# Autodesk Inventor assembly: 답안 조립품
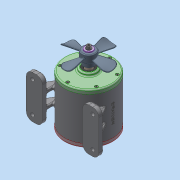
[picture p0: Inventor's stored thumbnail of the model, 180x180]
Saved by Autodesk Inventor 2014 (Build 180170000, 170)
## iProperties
Created: 2024-02
Part Number: 답안 조립품
Document SubType Name: Assembly
Designer: dg
Mass: 3108.48 g
Surface Area: 2333.46 cm^2
Volume: 963.013 cm^3
Density: 3.22787 g/cm^3
Author: dg
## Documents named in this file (20)
- C:\Users\dg\Desktop\640204V1011\답안 조립품.iam
- C:\Users\dg\Desktop\640204V1011\본체.ipt
- C:\Users\dg\Desktop\640204V1011\메인 기어 축.ipt
- C:\Users\dg\Desktop\640204V1011\서브 기어 축.ipt
- C:\Users\dg\Desktop\640204V1011\베어링 608.ipt
- C:\Users\dg\Desktop\640204V1011\베어링 6903.ipt
- C:\Users\dg\Desktop\640204V1011\뒷커버.ipt
- C:\Users\dg\Desktop\640204V1011\부시.ipt
- C:\Users\dg\Desktop\640204V1011\슬라이더.ipt
- C:\Users\dg\Desktop\640204V1011\앞커버.ipt
- C:\Users\dg\Desktop\640204V1011\오일 실 8 22 7.ipt
- C:\Users\dg\Desktop\640204V1011\오일 실 17 30 8.ipt
- C:\Users\dg\Desktop\640204V1011\키 5 x 5 x 24.ipt
- C:\Users\dg\Desktop\640204V1011\팬날개.ipt
- 팬날개.ipt
- C:\Users\dg\Desktop\640204V1011\육각 소켓 머리 볼트 M4 x 12.ipt
- C:\Users\dg\Desktop\640204V1011\앤드 캡.ipt
- C:\Users\dg\Desktop\640204V1011\육각 소켓 머리 볼트 M6 x 12.ipt
- C:\Users\dg\Desktop\640204V1011\가변스프링.ipt
- C:\Users\dg\Desktop\640204V1011\스프링 와셔 M6.ipt
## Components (1 placed, 1 different names)
1. 가변스프링:1
